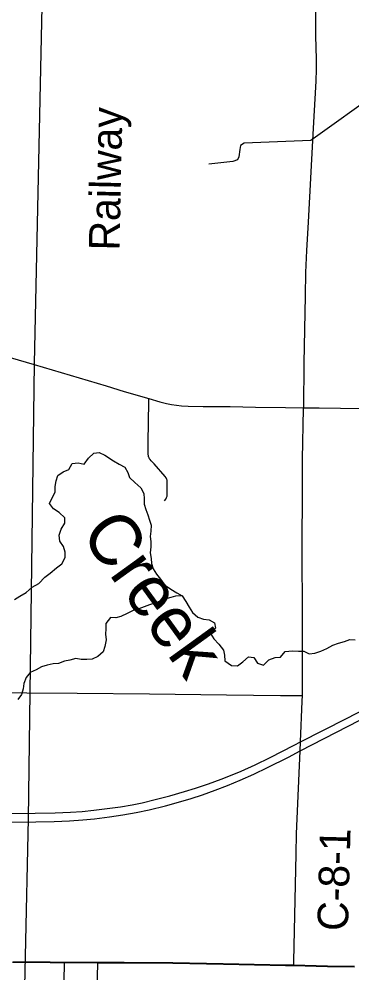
# Model space of a CAD drawing. Extents: x -21.7 to 34, y 0 to 22.
# Drawn here: x 25.906 to 26.522, y 18.47 to 20.235 of the extents above; entities that cross this region are included whole.
import ezdxf

# ---------------------------------------------------------------- set-up
doc = ezdxf.new("R2010")
doc.units = 0
for name, color, linetype in [('GM_X_Corporation', 7, 'Continuous'), ('GM_X_County_Road', 7, 'Continuous'), ('GM_X_County_Road_Text', 7, 'Continuous'), ('GM_X_Interchange_Ramps', 7, 'Continuous'), ('GM_X_Interstate_Route', 7, 'Continuous'), ('GM_X_Minor_River', 7, 'Continuous'), ('GM_X_Minor_River_Text', 7, 'Continuous'), ('GM_X_Rail_Line', 7, 'Continuous'), ('GM_X_Rail_Line_Text', 7, 'Continuous'), ('GM_X_Township_Road', 7, 'Continuous')]:
    doc.layers.add(name, color=color, linetype=linetype)

msp = doc.modelspace()

# ---------------------------------------------------------------- linework, layer by layer
at = {"layer": 'GM_X_Corporation'}
msp.add_lwpolyline([(25.9895, 18.4172), (25.9908, 18.4897), (26.0513, 18.4893), (26.0461, 18.2409)], dxfattribs=at)
at = {"layer": 'GM_X_County_Road'}
msp.add_line((25.9912, 18.4891), (26.0511, 18.4888), dxfattribs=at)
for points in [[(26.433, 19.5159), (26.434, 19.5982), (26.4362, 19.7226), (26.4372, 19.7662), (26.439, 19.8066), (26.4419, 19.8594), (26.447, 19.9526), (26.4512, 20.0334), (26.4559, 20.1203), (26.4565, 20.1421), (26.4565, 20.1607), (26.4554, 20.204), (26.4556, 20.2383), (26.4562, 20.3005), (26.4581, 20.4311), (26.4592, 20.5276), (26.4593, 20.5382)], [(25.6923, 19.668), (25.7051, 19.6643), (25.7379, 19.6545), (25.7766, 19.6429), (25.8599, 19.6177), (25.8898, 19.609), (25.9344, 19.5956), (26.0507, 19.5613), (26.0678, 19.5561)], [(26.0678, 19.5561), (26.1012, 19.546), (26.1465, 19.5327)], [(26.1465, 19.5327), (26.1669, 19.5267), (26.179, 19.5236), (26.1882, 19.5218), (26.1975, 19.5204), (26.2068, 19.5195), (26.2193, 19.5189), (26.2473, 19.5183), (26.297, 19.5179), (26.3436, 19.5171), (26.3996, 19.5163), (26.433, 19.5159)], [(26.4306, 18.9834), (26.4308, 18.9947), (26.4306, 19.0662), (26.4306, 19.1502), (26.4304, 19.2342), (26.4305, 19.3867), (26.4309, 19.4209), (26.4329, 19.5142), (26.433, 19.5159)], [(26.433, 19.5159), (26.4618, 19.5156), (26.5799, 19.5136), (26.6235, 19.5132), (26.723, 19.5118), (26.7727, 19.5112), (26.8505, 19.5102), (26.8847, 19.51), (26.9935, 19.509), (27.0806, 19.5079), (27.1241, 19.5072), (27.1832, 19.5062), (27.1963, 19.5062)], [(26.4146, 18.4834), (26.4148, 18.4911), (26.4191, 18.6902), (26.42, 18.7275), (26.4247, 18.8394), (26.4265, 18.8807), (26.4272, 18.8975), (26.4304, 18.973), (26.4306, 18.9834)], [(25.6651, 18.4908), (25.7559, 18.4905), (25.8958, 18.4896), (25.9642, 18.4893), (25.9912, 18.4891)], [(26.0511, 18.4888), (26.101, 18.4885), (26.1911, 18.4879), (26.2844, 18.4864), (26.3994, 18.4837), (26.4146, 18.4834)], [(26.4146, 18.4834), (26.4771, 18.4821), (26.5273, 18.4815)]]:
    msp.add_lwpolyline(points, dxfattribs=at)
at = {"layer": 'GM_X_Interchange_Ramps'}
for points in [[(26.527, 18.482), (26.4769, 18.4826), (26.4144, 18.484), (26.3992, 18.4843), (26.2842, 18.4869), (26.1909, 18.4884), (26.1008, 18.489), (25.964, 18.4899), (25.8956, 18.4901)], [(25.8956, 18.4901), (25.964, 18.4899), (26.1008, 18.489), (26.1909, 18.4884), (26.2842, 18.4869), (26.3992, 18.4843), (26.4144, 18.484), (26.4769, 18.4826), (26.527, 18.482)]]:
    msp.add_lwpolyline(points, dxfattribs=at)
at = {"layer": 'GM_X_Interstate_Route'}
for points in [[(25.8305, 18.7644), (25.9362, 18.7654), (25.9735, 18.7662), (26.0015, 18.7673), (26.0232, 18.7688), (26.0449, 18.7709), (26.0696, 18.7739), (26.0943, 18.7776), (26.1157, 18.7813), (26.134, 18.785), (26.1583, 18.7907), (26.1854, 18.7977), (26.2123, 18.8054), (26.2331, 18.8119), (26.2567, 18.8198), (26.2802, 18.8282), (26.3004, 18.8363), (26.3176, 18.8435), (26.343, 18.8552), (26.371, 18.8688), (26.4154, 18.8914), (26.4272, 18.8975), (26.5123, 18.9409), (26.5814, 18.9765)], [(25.8535, 18.749), (25.9375, 18.7496), (25.9717, 18.7502), (25.9996, 18.7514), (26.0244, 18.7531), (26.046, 18.7553), (26.0737, 18.7588), (26.0983, 18.7625), (26.1228, 18.7669), (26.1471, 18.772), (26.1773, 18.7793), (26.2012, 18.7858), (26.2251, 18.7929), (26.2457, 18.7996), (26.2691, 18.8079), (26.2923, 18.8168), (26.3153, 18.8264), (26.3408, 18.8378), (26.3659, 18.85), (26.4048, 18.8695), (26.4265, 18.8807), (26.5154, 18.9264), (26.6314, 18.9863)]]:
    msp.add_lwpolyline(points, dxfattribs=at)
at = {"layer": 'GM_X_Minor_River'}
for points in [[(26.5737, 20.1018), (26.4463, 20.0101), (26.3229, 20.0053), (26.3163, 20.0013), (26.3146, 19.9934), (26.3128, 19.9801), (26.3104, 19.9745), (26.302, 19.9712), (26.2578, 19.9665)], [(25.8981, 19.1607), (25.9077, 19.1673), (25.9193, 19.1739), (25.9309, 19.1839), (25.9432, 19.1908), (25.9541, 19.202), (25.9638, 19.2094), (25.9758, 19.2197), (25.9854, 19.2271), (25.9918, 19.2387), (25.9916, 19.2486), (25.9884, 19.2589), (25.9819, 19.2689), (25.9806, 19.28), (25.9843, 19.2913), (25.991, 19.3025), (25.9912, 19.312), (25.9808, 19.3221), (25.97, 19.3288), (25.963, 19.3384), (25.9674, 19.349), (25.9734, 19.3598), (25.9732, 19.3701), (25.975, 19.3803), (25.9783, 19.3901), (25.9879, 19.3971), (25.9983, 19.4018), (26.005, 19.4123), (26.0156, 19.4139), (26.027, 19.4114), (26.0348, 19.4222), (26.0445, 19.4319), (26.0548, 19.4332), (26.0653, 19.428), (26.081, 19.4178), (26.0918, 19.4115), (26.1019, 19.4059), (26.1074, 19.3959), (26.111, 19.3864), (26.1206, 19.3774), (26.1318, 19.3673), (26.1372, 19.3569), (26.1381, 19.3474), (26.1379, 19.3376), (26.1411, 19.3276), (26.1446, 19.3177), (26.1478, 19.3077), (26.151, 19.2982), (26.15, 19.2876), (26.149, 19.2777), (26.1503, 19.2682), (26.1504, 19.2583), (26.149, 19.247), (26.1511, 19.2371), (26.1516, 19.2276), (26.1544, 19.218), (26.161, 19.208), (26.168, 19.1983), (26.1757, 19.1883), (26.1873, 19.1801), (26.1981, 19.1734), (26.2079, 19.1678), (26.2148, 19.1574), (26.2214, 19.1467), (26.2273, 19.137), (26.2373, 19.1285), (26.2478, 19.1248), (26.258, 19.1234), (26.2682, 19.1179), (26.2698, 19.1076), (26.2605, 19.098), (26.2667, 19.0879), (26.2763, 19.0786)], [(26.2079, 19.1678), (26.1957, 19.1671), (26.1875, 19.1644), (26.1804, 19.1628), (26.1697, 19.1588), (26.1594, 19.1549), (26.1479, 19.151), (26.1376, 19.1474), (26.128, 19.1434), (26.1173, 19.1406), (26.1066, 19.1352), (26.095, 19.1294), (26.0855, 19.1273), (26.0756, 19.1275), (26.067, 19.1167), (26.0672, 19.1064), (26.0666, 19.0966), (26.0675, 19.0863), (26.0653, 19.0742), (26.062, 19.0644), (26.0519, 19.0555), (26.0416, 19.0505), (26.0317, 19.0499), (26.0211, 19.0502), (26.0112, 19.0515), (26.0002, 19.0487), (25.9903, 19.0467), (25.9795, 19.0424), (25.9697, 19.0422), (25.9586, 19.0394), (25.9479, 19.0366), (25.9379, 19.0308), (25.9268, 19.0261), (25.9194, 19.0164), (25.9153, 19.0055), (25.9139, 18.9956), (25.911, 18.9854), (25.9044, 18.9757)], [(26.2763, 19.0786), (26.2848, 19.0674), (26.2865, 19.0579), (26.2874, 19.0476), (26.2993, 19.039), (26.3107, 19.038), (26.3203, 19.0457), (26.3312, 19.055), (26.341, 19.0536), (26.3476, 19.0429), (26.3585, 19.0392), (26.3686, 19.0492), (26.3801, 19.0539), (26.39, 19.0544), (26.3986, 19.0645), (26.4122, 19.0657), (26.4236, 19.0655), (26.4331, 19.0656), (26.4432, 19.0601), (26.4535, 19.0618), (26.465, 19.0653), (26.4757, 19.07), (26.4869, 19.0766), (26.4972, 19.0801), (26.5083, 19.0833), (26.5182, 19.0869), (26.5281, 19.0863)]]:
    msp.add_lwpolyline(points, dxfattribs=at)
at = {"layer": 'GM_X_Rail_Line'}
msp.add_lwpolyline([(25.8368, 14.1), (25.8424, 14.4841), (25.8672, 15.4825), (25.8776, 16.2603), (25.8795, 16.4862), (25.8906, 16.927), (25.8907, 16.9438), (25.8961, 17.4845), (25.9239, 18.7551), (25.935, 19.5978), (25.9554, 20.5461), (25.9616, 20.9)], dxfattribs=at)
at = {"layer": 'GM_X_Township_Road'}
for points in [[(25.6923, 19.668), (25.7051, 19.6643), (25.7379, 19.6545), (25.7766, 19.6429), (25.8599, 19.6177), (25.8898, 19.609), (25.9344, 19.5956), (26.0507, 19.5613), (26.0678, 19.5561)], [(26.0678, 19.5561), (26.1012, 19.546), (26.1465, 19.5327)], [(26.1755, 19.3436), (26.1777, 19.3463), (26.1795, 19.3494), (26.18, 19.3508), (26.1804, 19.3522), (26.1806, 19.354), (26.1807, 19.3578), (26.1806, 19.3612), (26.1807, 19.3735), (26.1806, 19.3798), (26.1804, 19.3815), (26.1801, 19.3831), (26.1795, 19.3848), (26.1788, 19.3861), (26.177, 19.3888), (26.1562, 19.4121), (26.151, 19.4175), (26.1488, 19.4202), (26.148, 19.4213), (26.1471, 19.4229), (26.1466, 19.4239), (26.1461, 19.4254), (26.1458, 19.4267), (26.1453, 19.4296), (26.1451, 19.4327), (26.1455, 19.4515), (26.1464, 19.5265), (26.1465, 19.5327)], [(26.1465, 19.5327), (26.1669, 19.5267), (26.179, 19.5236), (26.1882, 19.5218), (26.1975, 19.5204), (26.2068, 19.5195), (26.2193, 19.5189), (26.2473, 19.5183), (26.297, 19.5179), (26.3436, 19.5171), (26.3996, 19.5163), (26.433, 19.5159)], [(26.433, 19.5159), (26.4618, 19.5156), (26.5799, 19.5136), (26.6235, 19.5132), (26.723, 19.5118), (26.7727, 19.5112), (26.8505, 19.5102), (26.8847, 19.51), (26.9935, 19.509), (27.0806, 19.5079), (27.1241, 19.5072), (27.1832, 19.5062), (27.1963, 19.5062)], [(25.6767, 19.0344), (25.6828, 19.0341), (25.6921, 19.0333), (25.6983, 19.0323), (25.7044, 19.0308), (25.7104, 19.0289), (25.7191, 19.0255), (25.7333, 19.0189), (25.7557, 19.0082), (25.7671, 19.0033), (25.7758, 19), (25.7846, 18.9972), (25.7936, 18.9949), (25.8027, 18.993), (25.8149, 18.9912), (25.8273, 18.9901), (25.8428, 18.9893), (25.8676, 18.9888), (25.9207, 18.9884)], [(25.9207, 18.9884), (26.0138, 18.9877), (26.1475, 18.9862), (26.2905, 18.9845), (26.39, 18.9833), (26.4211, 18.9835), (26.4242, 18.9835), (26.4306, 18.9834)]]:
    msp.add_lwpolyline(points, dxfattribs=at)

# ---------------------------------------------------------------- texts
at = {"layer": 'GM_X_County_Road_Text'}
msp.add_text('C-8-1', height=0.05682, rotation=88.5233, dxfattribs=at).set_placement((26.5149, 18.547))
at = {"layer": 'GM_X_Minor_River_Text'}
msp.add_text('Creek', height=0.09476, rotation=305.8588, dxfattribs=at).set_placement((26.0182, 19.2825))
at = {"layer": 'GM_X_Rail_Line_Text'}
msp.add_text('Railway', height=0.05663, rotation=88.7614, dxfattribs=at).set_placement((26.0921, 19.8062))

doc.saveas('drawing.dxf')
